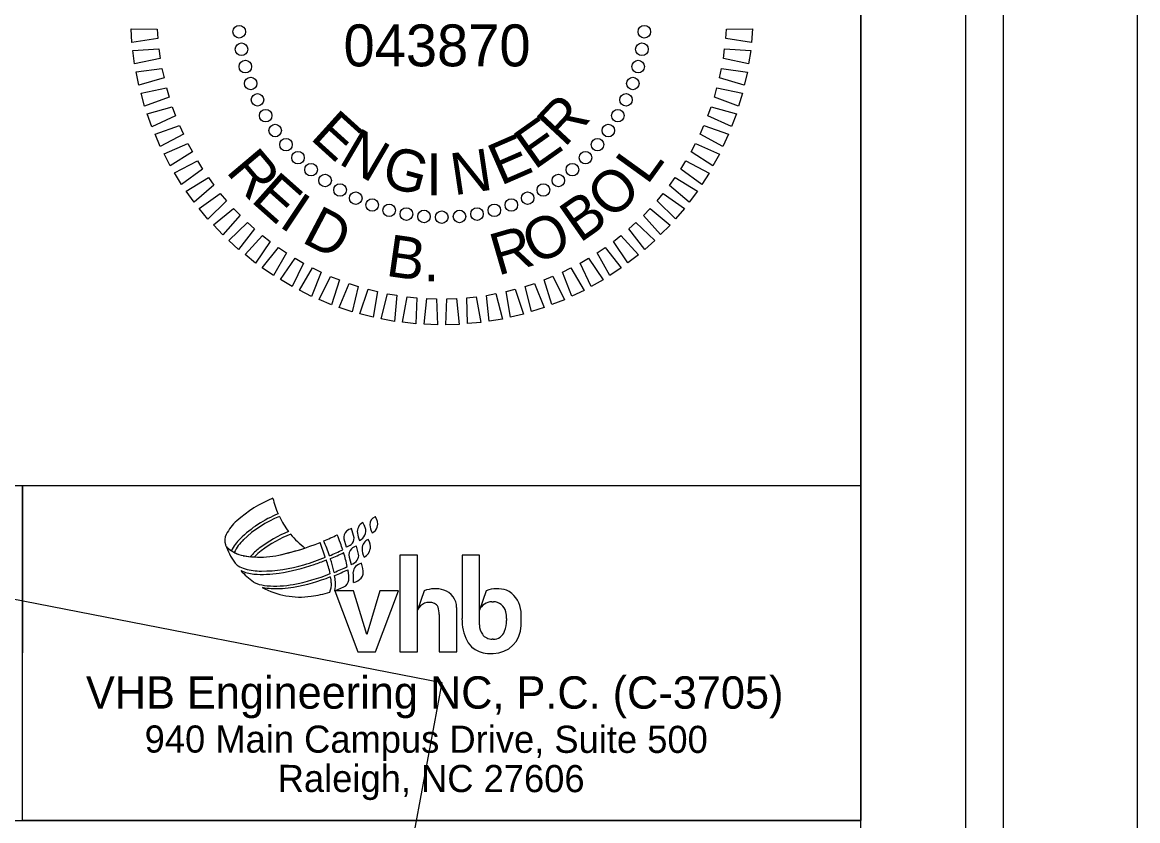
# Model space of a CAD drawing. Extents: x 1632447 to 1634147, y 883210 to 885181.
# Drawn here: x 1634013.8 to 1634146.9, y 884795.1 to 884890.3 of the extents above; entities that cross this region are included whole.
import ezdxf

# ---------------------------------------------------------------- set-up
doc = ezdxf.new("R2010")
doc.units = 0
for name, color, linetype in [('Default', 7, 'Continuous'), ('Scratch_Level_8', 7, 'Continuous'), ('Sheet PE Seal Cell', 7, 'Continuous'), ('Sheet Plan And Profile CELL', 7, 'Continuous'), ('Sheet Plot Border Inside CELL', 7, 'Continuous'), ('Sheet Plot Border Outside CELL', 7, 'Continuous'), ('Sheet Profile CELL', 7, 'Continuous'), ('Stewart Plot Border Xerox6279 and LJ5000', 7, 'Continuous')]:
    doc.layers.add(name, color=color, linetype=linetype)

msp = doc.modelspace()

# ---------------------------------------------------------------- linework, layer by layer
at = {"layer": 'Default'}
for p, q in [((1634053.41, 884828.8), (1634053.1, 884829.91)), ((1634052.2, 884828.69), (1634052.48, 884827.71)), ((1634049.98, 884826.49), (1634049.35, 884828.25)), ((1634053.95, 884826.84), (1634053.68, 884827.81)), ((1634052.81, 884826.51), (1634053.06, 884825.61)), ((1634060.96, 884826.72), (1634058.88, 884826.72)), ((1634058.88, 884826.72), (1634058.88, 884815.19)), ((1634068.36, 884826.72), (1634066.28, 884826.72)), ((1634066.28, 884826.72), (1634066.28, 884819.16)), ((1634051.13, 884822.49), (1634052.19, 884822.96)), ((1634053.35, 884822.49), (1634051.13, 884822.49)), ((1634051.13, 884822.49), (1634053.87, 884815.19)), ((1634054.91, 884817.28), (1634053.35, 884822.49)), ((1634056.48, 884822.49), (1634054.91, 884817.28)), ((1634055.96, 884815.19), (1634058.7, 884822.49)), ((1634058.7, 884822.49), (1634056.48, 884822.49)), ((1634061.77, 884822.49), (1634060.96, 884820.18)), ((1634069.17, 884822.49), (1634068.36, 884820.18)), ((1634065.65, 884815.19), (1634065.65, 884820.48)), ((1634069.83, 884821.17), (1634070.02, 884821.17)), ((1634063.57, 884819.65), (1634063.57, 884815.19)), ((1634071.59, 884819.16), (1634071.59, 884818.94)), ((1634073.34, 884818.36), (1634073.34, 884819.67)), ((1634070.01, 884816.71), (1634069.88, 884816.71)), ((1634053.87, 884815.19), (1634055.96, 884815.19)), ((1634058.88, 884815.19), (1634060.96, 884815.19)), ((1634063.57, 884815.19), (1634065.65, 884815.19)), ((1634069.57, 884814.99), (1634069.98, 884814.99)), ((1633913.83, 884795.06), (1634113.86, 884795.06)), ((1633913.83, 884795.06), (1634113.86, 884795.06))]:
    msp.add_line(p, q, dxfattribs=at)
msp.add_lwpolyline([(1634013.86, 884835.06), (1634113.86, 884835.06), (1634113.86, 884795.06), (1634013.86, 884795.06)], close=True, dxfattribs=at)
for points in [[(1634060.96, 884815.19), (1634060.96, 884820.18), (1634060.96, 884826.72)], [(1634068.36, 884818.41), (1634068.36, 884820.18), (1634068.36, 884826.72)]]:
    msp.add_lwpolyline(points, dxfattribs=at)
for centre, major_axis, start_param, end_param in [((1634049.05, 884820.18), (14.36, 0), 1.950459, 2.306295), ((1634054.02, 884835.96), (10.58, 0), 3.374816, 3.559712), ((1634049.61, 884818.71), (13.98, 0), 1.955908, 2.345415), ((1634049.61, 884818.71), (13.63, 0), 1.954608, 2.331375), ((1634054.02, 884835.96), (10.58, 0), 3.593328, 3.791245), ((1634056.28, 884830.41), (0.982, 0), 1.950799, 3.19085), ((1634054.87, 884830.46), (1.36, 0), 6.010502, 6.978239), ((1634043.32, 884826.52), (5.82, 0), 2.306295, 2.663056), ((1634053.4, 884828.66), (1.28, 0), 1.805558, 2.340862), ((1634055.07, 884829.51), (1.28, 0), 2.069357, 3.26373), ((1634053.52, 884829.64), (1.28, 0), 5.158115, 6.583255), ((1634052.36, 884829.28), (2.49, 0), 0.300085, 0.573578), ((1634057.79, 884830.49), (2.49, 0), 3.190836, 3.597778), ((1634055.16, 884830.37), (1.06, 0), 5.088672, 6.010509), ((1634039.5, 884828.5), (1.51, 0), 2.663056, 3.487291), ((1634043.53, 884824.92), (5.29, 0), 2.345415, 2.685879), ((1634043.6, 884825.03), (4.91, 0), 2.331375, 2.717794), ((1634051.29, 884815.56), (15.11, 0), 1.956929, 2.223843), ((1634051.29, 884815.56), (14.73, 0), 1.949325, 2.223843), ((1634054.02, 884835.96), (10.58, 0), 3.829221, 4.05458), ((1634038.1, 884856.3), (30.23, 0), 5.110242, 5.168312), ((1634014.71, 884814.43), (37.79, 0), 0.330018, 0.379866), ((1634014.71, 884814.43), (39.54, 0), 0.355324, 0.381952), ((1634053.21, 884828.85), (1.02, 0), 2.340862, 3.293303), ((1634052.39, 884828.77), (1.02, 0), 5.445151, 6.311085), ((1634056.27, 884829.66), (2.49, 0), 3.26373, 3.631752), ((1634055.58, 884827.5), (1.21, 0), 1.982585, 3.114577), ((1634053.78, 884827.72), (1.59, 0), 6.124862, 6.873863), ((1634046.96, 884831.19), (9.45, 0), 3.487291, 3.49224), ((1634038.8, 884828.2), (0.756, 0), 3.492238, 3.942132), ((1634038.8, 884828.2), (0.756, 0), 3.492238, 3.942132), ((1634046.96, 884831.19), (9.45, 0), 3.492238, 3.737263), ((1634040.86, 884830.32), (3.7, 0), 3.942115, 4.117328), ((1634040.86, 884830.32), (3.7, 0), 3.942115, 4.535322), ((1634040.86, 884830.32), (3.7, 0), 4.225969, 4.535322), ((1634046.24, 884822.17), (6.8, 0), 2.223843, 2.440018), ((1634046.24, 884822.17), (6.42, 0), 2.223843, 2.396036), ((1634038.1, 884856.3), (30.23, 0), 4.923489, 5.093727), ((1634038.1, 884856.3), (30.23, 0), 4.923489, 5.030725), ((1634038.1, 884856.3), (32.11, 0), 5.107726, 5.162272), ((1634038.1, 884856.3), (32.47, 0), 5.106941, 5.160619), ((1634033.51, 884821.4), (19.49, 0), 0.312292, 0.355324), ((1634033.51, 884821.4), (19.49, 0), 0.205325, 0.293478), ((1634052.21, 884828.97), (1.28, 0), 4.922279, 5.445148), ((1634053.76, 884826.76), (0.982, 0), 2.294387, 3.400315), ((1634054.06, 884826.42), (1.44, 0), 1.838184, 2.294391), ((1634056.49, 884827.47), (2.12, 0), 3.114567, 3.617561), ((1634054.08, 884827.68), (1.28, 0), 5.137017, 6.124854), ((1634040.4, 884826.74), (1.51, 0), 3.737263, 4.155114), ((1634042.13, 884837.46), (10.96, 0), 4.535322, 4.613027), ((1634042.13, 884837.46), (10.96, 0), 4.535322, 4.657076), ((1634042.13, 884837.46), (10.96, 0), 4.657076, 4.923489), ((1634042.13, 884837.46), (10.96, 0), 4.657076, 4.923489), ((1634040.78, 884848.49), (24.18, 0), 4.866042, 5.043468), ((1634038.1, 884856.3), (32.1, 0), 5.007435, 5.091777), ((1634038.1, 884856.3), (32.44, 0), 5.043468, 5.091439), ((1634040.15, 884822.56), (10.58, 0), 0.186675, 0.34709), ((1634014.71, 884814.43), (37.79, 0), 0.309699, 0.320394), ((1634040.15, 884822.56), (11.08, 0), 0.192744, 0.309699), ((1634052.61, 884826.98), (1.44, 0), 5.034707, 5.66976), ((1634054.99, 884823.78), (2.12, 0), 1.905419, 2.288613), ((1634052.98, 884826.72), (0.982, 0), 5.669754, 6.410867), ((1634050.79, 884824.57), (3.7, 0), 6.258511, 6.615609), ((1634041.28, 884828.15), (3.17, 0), 4.155114, 4.433304), ((1634041.87, 884829.16), (4.69, 0), 4.281835, 4.626581), ((1634046.96, 884831.19), (9.45, 0), 3.869789, 4.084312), ((1634042.32, 884831.78), (6.95, 0), 4.433304, 4.717272), ((1634042.55, 884837.06), (12.62, 0), 4.626581, 4.866042), ((1634042.26, 884842.59), (17.76, 0), 4.717272, 5.007435), ((1634042.02, 884845.53), (22.67, 0), 4.896065, 5.098239), ((1634038.1, 884856.3), (34.16, 0), 5.100586, 5.150688), ((1634038.1, 884856.3), (34.53, 0), 5.098273, 5.148033), ((1634040.15, 884822.56), (11.08, 0), 0.08898, 0.158557), ((1634033.51, 884821.4), (19.49, 0), 0.162521, 0.185756), ((1634049.76, 884824.06), (3.02, 0), 6.17953, 6.445706), ((1634054.14, 884824.75), (0.831, 0), 2.288613, 3.208516), ((1634047.09, 884823.88), (6.27, 0), 6.218327, 6.411973), ((1634053.67, 884824.6), (0.831, 0), 5.49053, 6.137671), ((1634042.3, 884824.77), (1.51, 0), 4.084312, 4.375641), ((1634043.43, 884827.98), (4.91, 0), 4.375641, 4.631331), ((1634043.99, 884834.91), (11.86, 0), 4.631331, 4.896065), ((1634042.7, 884843.8), (21.16, 0), 4.878361, 5.095384), ((1634048.44, 884823.24), (2.27, 0), 5.862276, 6.364042), ((1634040.15, 884822.56), (10.58, 0), 0.080866, 0.152313), ((1634047.42, 884823.21), (3.78, 0), 6.089473, 6.37216), ((1634051.79, 884823.85), (0.982, 0), 5.129856, 6.17953), ((1634052.77, 884825.51), (2.12, 0), 4.991009, 5.49053), ((1634043.83, 884829.71), (6.95, 0), 4.511808, 4.670453), ((1634046.96, 884831.19), (9.45, 0), 4.213149, 4.853258), ((1634044.07, 884835.6), (12.85, 0), 4.670453, 4.878361), ((1634046.01, 884837.92), (16.25, 0), 4.853258, 4.99278), ((1634063.07, 884819.22), (3.51, 0), 1.271815, 1.948427), ((1634063.45, 884820.48), (2.19, 0), 6.283185, 7.555001), ((1634070.46, 884819.22), (3.51, 0), 1.243417, 1.948427), ((1634071.01, 884820.83), (1.81, 0), 0.841181, 1.243417), ((1634069.98, 884819.67), (3.36, 0), 0, 0.841181), ((1634062.4, 884819.51), (-1.59, 0), 4.330931, 5.84316), ((1634062.71, 884820.28), (-0.756, 0), 3.478495, 4.330931), ((1634060.92, 884819.65), (2.65, 0), 0, 0.336903), ((1634069.83, 884819.58), (1.59, 0), 1.570796, 2.75299), ((1634070.02, 884819.66), (1.51, 0), 0.218399, 1.570796), ((1634072.32, 884819.16), (-6.05, 0), 0, 0.452165), ((1634067.81, 884819.16), (3.78, 0), 6.283185, 6.501584), ((1634070.25, 884818.41), (-1.89, 0), 6.283185, 6.906012), ((1634069.98, 884818.36), (3.36, 0), 4.712389, 6.283185), ((1634070.01, 884818.14), (1.44, 0), 4.712389, 5.93764), ((1634067.81, 884818.94), (3.78, 0), 5.93764, 6.283185), ((1634069.06, 884817.58), (-2.42, 0), 0.452165, 0.946963), ((1634069.88, 884818.14), (-1.44, 0), 0.622827, 1.570796), ((1634069.57, 884818.29), (-3.29, 0), 0.946963, 1.570796)]:
    msp.add_ellipse(centre, major_axis=major_axis, ratio=0.999914, start_param=start_param, end_param=end_param, dxfattribs=at)
at = {"layer": 'Scratch_Level_8'}
msp.add_lwpolyline([(1632663.86, 883947.61), (1632663.86, 885084.12), (1634063.86, 884811.56), (1634013.86, 884541.53), (1634013.86, 883947.61)], close=True, dxfattribs=at)
at = {"layer": 'Sheet PE Seal Cell'}
for points in [[(1634030, 884888.37), (1634026.91, 884887.92), (1634026.83, 884889.53), (1634029.91, 884889.51)], [(1634097.81, 884889.51), (1634100.93, 884889.52), (1634100.79, 884887.91), (1634097.73, 884888.37)], [(1634030.29, 884886.01), (1634027.24, 884885.35), (1634027.04, 884886.95), (1634030.12, 884887.14)], [(1634097.6, 884887.14), (1634100.71, 884886.94), (1634100.46, 884885.35), (1634097.45, 884886.01)], [(1634030.74, 884883.68), (1634027.74, 884882.81), (1634027.44, 884884.39), (1634030.49, 884884.8)], [(1634097.22, 884884.8), (1634100.32, 884884.38), (1634099.95, 884882.81), (1634096.99, 884883.68)], [(1634031.35, 884881.39), (1634028.42, 884880.31), (1634028.01, 884881.87), (1634031.03, 884882.49)], [(1634096.69, 884882.49), (1634099.75, 884881.86), (1634099.27, 884880.31), (1634096.38, 884881.39)], [(1634032.12, 884879.15), (1634029.28, 884877.86), (1634028.75, 884879.39), (1634031.72, 884880.22)], [(1634095.99, 884880.22), (1634099, 884879.38), (1634098.42, 884877.87), (1634095.61, 884879.14)], [(1634033.05, 884876.96), (1634030.3, 884875.48), (1634029.67, 884876.97), (1634032.58, 884878)], [(1634095.14, 884878.01), (1634098.08, 884876.96), (1634097.4, 884875.49), (1634094.68, 884876.96)], [(1634034.12, 884874.85), (1634031.49, 884873.18), (1634030.75, 884874.62), (1634033.58, 884875.85)], [(1634094.14, 884875.86), (1634097, 884874.6), (1634096.21, 884873.19), (1634093.61, 884874.84)], [(1634035.34, 884872.81), (1634032.83, 884870.96), (1634032, 884872.35), (1634034.73, 884873.78)], [(1634092.99, 884873.78), (1634095.75, 884872.33), (1634094.87, 884870.98), (1634092.39, 884872.81)], [(1634036.7, 884870.87), (1634034.32, 884868.85), (1634033.4, 884870.17), (1634036.03, 884871.79)], [(1634091.69, 884871.79), (1634094.35, 884870.16), (1634093.38, 884868.86), (1634091.03, 884870.86)], [(1634038.19, 884869.03), (1634035.96, 884866.84), (1634034.95, 884868.1), (1634037.45, 884869.9)], [(1634090.26, 884869.9), (1634092.8, 884868.08), (1634091.74, 884866.86), (1634089.54, 884869.02)], [(1634039.81, 884867.29), (1634037.74, 884864.96), (1634036.64, 884866.14), (1634039.01, 884868.11)], [(1634088.71, 884868.11), (1634091.11, 884866.12), (1634089.97, 884864.98), (1634087.92, 884867.28)], [(1634041.55, 884865.67), (1634039.64, 884863.2), (1634038.46, 884864.3), (1634040.69, 884866.43)], [(1634087.03, 884866.43), (1634089.29, 884864.28), (1634088.07, 884863.22), (1634086.18, 884865.66)], [(1634043.39, 884864.18), (1634041.66, 884861.58), (1634040.4, 884862.6), (1634042.48, 884864.87)], [(1634085.24, 884864.88), (1634087.34, 884862.57), (1634086.05, 884861.6), (1634084.34, 884864.17)], [(1634045.33, 884862.81), (1634043.79, 884860.1), (1634042.46, 884861.03), (1634044.38, 884863.45)], [(1634083.34, 884863.45), (1634085.28, 884861), (1634083.92, 884860.12), (1634082.4, 884862.81)], [(1634047.36, 884861.59), (1634046.01, 884858.78), (1634044.63, 884859.61), (1634046.37, 884862.16)], [(1634081.35, 884862.16), (1634083.11, 884859.58), (1634081.7, 884858.8), (1634080.36, 884861.58)], [(1634049.48, 884860.51), (1634048.33, 884857.61), (1634046.89, 884858.35), (1634048.45, 884861.01)], [(1634079.27, 884861.01), (1634080.85, 884858.32), (1634079.39, 884857.64), (1634078.25, 884860.5)], [(1634051.66, 884859.58), (1634050.71, 884856.61), (1634049.23, 884857.24), (1634050.6, 884860)], [(1634053.9, 884858.81), (1634053.17, 884855.78), (1634051.64, 884856.3), (1634052.81, 884859.16)], [(1634074.91, 884859.16), (1634076.09, 884856.28), (1634074.55, 884855.8), (1634073.82, 884858.8)], [(1634077.12, 884860.01), (1634078.51, 884857.21), (1634077, 884856.64), (1634076.07, 884859.58)], [(1634056.19, 884858.19), (1634055.67, 884855.12), (1634054.11, 884855.54), (1634055.08, 884858.46)], [(1634058.52, 884857.74), (1634058.22, 884854.63), (1634056.63, 884854.94), (1634057.4, 884857.93)], [(1634060.88, 884857.45), (1634060.79, 884854.33), (1634059.18, 884854.53), (1634059.74, 884857.56)], [(1634067.98, 884857.57), (1634068.54, 884854.5), (1634066.93, 884854.36), (1634066.85, 884857.44)], [(1634070.33, 884857.94), (1634071.1, 884854.91), (1634069.5, 884854.66), (1634069.2, 884857.73)], [(1634072.64, 884858.47), (1634073.62, 884855.51), (1634072.05, 884855.14), (1634071.53, 884858.19)], [(1634063.25, 884857.32), (1634063.37, 884854.2), (1634061.76, 884854.29), (1634062.1, 884857.36)], [(1634065.62, 884857.36), (1634065.96, 884854.26), (1634064.35, 884854.23), (1634064.48, 884857.32)]]:
    msp.add_lwpolyline(points, close=True, dxfattribs=at)
for centre in [(1634039.71, 884889.19), (1634088.02, 884889.19), (1634039.98, 884887.1), (1634087.74, 884887.1), (1634040.44, 884885.03), (1634087.29, 884885.03), (1634041.08, 884883.01), (1634086.65, 884883.01), (1634041.89, 884881.06), (1634085.84, 884881.06), (1634042.86, 884879.18), (1634084.86, 884879.18), (1634044, 884877.4), (1634083.73, 884877.4), (1634045.29, 884875.72), (1634082.44, 884875.72), (1634046.72, 884874.16), (1634081.01, 884874.16), (1634048.28, 884872.73), (1634049.95, 884871.44), (1634077.77, 884871.44), (1634079.45, 884872.73), (1634051.74, 884870.31), (1634075.99, 884870.31), (1634053.61, 884869.33), (1634074.11, 884869.33), (1634055.57, 884868.52), (1634057.59, 884867.88), (1634059.65, 884867.43), (1634068.07, 884867.43), (1634070.14, 884867.88), (1634072.16, 884868.52), (1634061.75, 884867.15), (1634063.86, 884867.06), (1634065.98, 884867.15)]:
    msp.add_circle(centre, 0.75, dxfattribs=at)
at = {"layer": 'Sheet Plan And Profile CELL'}
for p, q in [((1634013.86, 884835.06), (1634013.84, 884795.06)), ((1633913.83, 884795.06), (1634113.86, 884795.06))]:
    msp.add_line(p, q, dxfattribs=at)
at = {"layer": 'Sheet Plot Border Inside CELL'}
msp.add_lwpolyline([(1634126.36, 884975.16), (1632459.86, 884975.16), (1632459.86, 883920.06), (1634126.36, 883920.06)], close=True, dxfattribs=at)
at = {"layer": 'Sheet Plot Border Outside CELL'}
msp.add_lwpolyline([(1634130.86, 884997.61), (1632446.86, 884997.61), (1632446.86, 883897.61), (1634130.86, 883897.61)], close=True, dxfattribs=at)
at = {"layer": 'Sheet Profile CELL'}
msp.add_line((1634113.86, 884947.56), (1634113.86, 884835.06), dxfattribs=at)
msp.add_lwpolyline([(1634113.86, 884972.61), (1632613.86, 884972.61), (1632613.86, 883922.61), (1634113.86, 883922.61)], close=True, dxfattribs=at)
msp.add_lwpolyline([(1633913.81, 884947.56), (1633913.81, 884835.06), (1634113.86, 884835.06)], dxfattribs=at)
at = {"layer": 'Stewart Plot Border Xerox6279 and LJ5000'}
msp.add_lwpolyline([(1632446.86, 883897.61), (1634146.86, 883897.61), (1634146.86, 884997.61), (1632446.86, 884997.61)], close=True, dxfattribs=at)

# ---------------------------------------------------------------- texts
at = {"layer": 'Default'}
for s, height, rotation, p in [('VHB Engineering NC, P.C. (C-3705)', 3.8596, 360, (1634021.43, 884808.42)), ('940 Main Campus Drive, Suite 500', 3.2388, 359.9612, (1634028.43, 884803.18)), ('Raleigh, NC 27606', 3.2388, 359.9612, (1634044.3, 884798.48))]:
    msp.add_text(s, height=height, rotation=rotation, dxfattribs=at).set_placement(p)
at = {"layer": 'Sheet PE Seal Cell'}
msp.add_text('043870', height=5, dxfattribs=at).set_placement((1634052.15, 884885.06))
for s, rotation, p in [('R', 47.043, (1634078.5, 884875.29)), ('E', 317.8506, (1634048.05, 884876.45)), ('E', 35.2807, (1634074.92, 884872.64)), ('N', 329.6129, (1634051.41, 884873.54)), ('E', 23.5185, (1634070.89, 884870.78)), ('R', 310.1625, (1634038.03, 884872.49)), ('G', 344.6629, (1634056.46, 884870.92)), ('N', 8.4684, (1634065.32, 884869.66)), ('I', 359.713, (1634062, 884869.69)), ('L', 54.176, (1634088.37, 884870.8)), ('E', 318.3712, (1634040.98, 884869)), ('O', 43.4508, (1634084.13, 884866.6)), ('I', 326.3511, (1634044.3, 884866.04)), ('B', 35.1087, (1634080.33, 884863.92)), ('D', 332.291, (1634047.02, 884864.15)), ('O', 24.3836, (1634074.94, 884861.33)), ('R', 16.1749, (1634070.55, 884860.06)), ('B', 351.8635, (1634057.09, 884860.08)), ('.', 0.2056, (1634061.69, 884859.42))]:
    msp.add_text(s, height=5, rotation=rotation, dxfattribs=at).set_placement(p)

doc.saveas('drawing.dxf')
